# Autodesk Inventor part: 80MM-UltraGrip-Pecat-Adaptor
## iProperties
Created: 2012-05
Part Number: 80MM-UltraGrip-Pecat-Adaptor
Document SubType Name: Modeling
Designer: D Cole
Density: 1 g/cm^3
Author: D Cole
